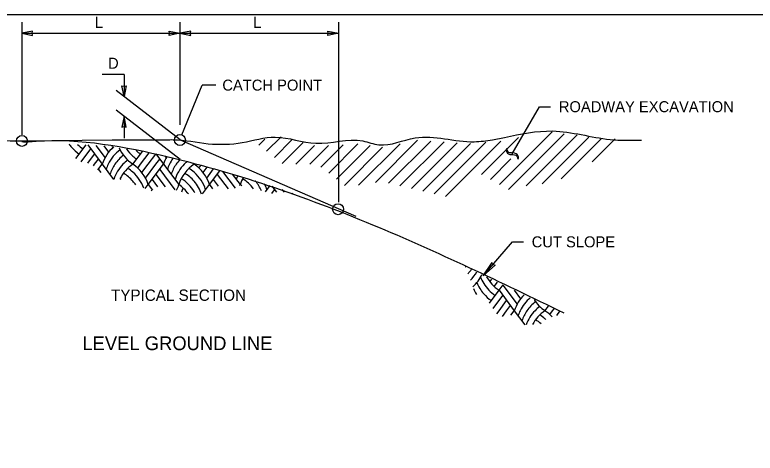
# Model space of a CAD drawing. Extents: x 99862 to 103151, y 100000 to 102076.
# Drawn here: x 100486 to 101562, y 101437 to 102076 of the extents above; entities that cross this region are included whole.
import ezdxf

# ---------------------------------------------------------------- set-up
doc = ezdxf.new("R2010")
doc.units = 0
for name, color, linetype in [('Level 1', 7, 'Continuous'), ('Level 14', 7, 'Continuous'), ('Level 15', 7, 'Continuous'), ('Level 16', 7, 'Continuous'), ('Level 17', 7, 'Continuous'), ('Level 20', 7, 'Continuous'), ('Level 4', 7, 'Continuous')]:
    doc.layers.add(name, color=color, linetype=linetype)

msp = doc.modelspace()

# ---------------------------------------------------------------- linework, layer by layer
at = {"layer": 'Level 1'}
msp.add_lwpolyline([(99862, 99999.5), (103151, 99999.5), (103151, 102075.5), (99862, 102075.5)], close=True, dxfattribs=at)
msp.add_spline([(100496.05863745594, 101891.01354403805), (100500.70108471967, 101890.4235694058), (100504.88457282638, 101890.66486915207), (100697.00538377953, 101871.58962349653), (101005.90092316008, 101770.05218203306), (101284.27137914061, 101641.69274742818)], degree=3, dxfattribs=at)
at = {"layer": 'Level 14'}
msp.add_circle((100495.98320228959, 101891.9961635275), 8, dxfattribs=at)
at = {"layer": 'Level 15'}
for p, q in [((100495.86601442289, 102064.5580484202), (100495.86601442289, 102024.27183196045)), ((100725.79867422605, 102064.5580484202), (100725.79867422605, 101915.37950221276)), ((100956.53789870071, 102064.5580484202), (100956.53789870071, 101802.89925094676)), ((100495.86601442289, 102048.5580484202), (100725.79867422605, 102048.5580484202)), ((100725.79867422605, 102048.5580484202), (100925.76532916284, 102048.5580484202)), ((100925.76532916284, 102048.5580484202), (100956.53789870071, 102048.5580484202)), ((100495.86601442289, 102024.27183196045), (100495.86601442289, 101900.69973032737)), ((100644.49165007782, 101988.4719941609), (100612.49165007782, 101988.4719941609)), ((100644.49165007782, 101988.4719941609), (100644.49165007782, 101956.4719941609)), ((100728.80250451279, 101900.68710735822), (100758.1635567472, 101973.16186250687)), ((100778.01844406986, 101973.16186250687), (100758.1635567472, 101973.16186250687)), ((100726.13895795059, 101893.31169181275), (100633.14329276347, 101965.25079774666)), ((101209.18553844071, 101873.14949087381), (101248.80950513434, 101941.78021440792)), ((101248.81060001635, 101941.78036938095), (101264.81060001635, 101941.78036938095)), ((100726.13895795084, 101864.74905572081), (100633.14329276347, 101936.68816165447)), ((100644.49165007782, 101927.9093580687), (100644.49165007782, 101895.9093580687)), ((101167.01985588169, 101695.75861149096), (101209.36149090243, 101745.07580875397)), ((101209.3623586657, 101745.07580783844), (101225.3623586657, 101745.07580783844))]:
    msp.add_line(p, q, dxfattribs=at)
for points in [[(100495.86601442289, 102048.5580484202), (100511.5910144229, 102045.47404842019), (100510.8630144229, 102048.5580484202), (100511.5910144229, 102051.6420484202)], [(100725.79867422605, 102048.5580484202), (100710.07367422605, 102045.47404842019), (100710.80167422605, 102048.5580484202), (100710.07367422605, 102051.6420484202)], [(100725.79867422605, 102048.5580484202), (100741.52367422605, 102045.47404842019), (100740.79567422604, 102048.5580484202), (100741.52367422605, 102051.6420484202)], [(100956.53789870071, 102048.5580484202), (100940.81289870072, 102045.47404842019), (100941.54089870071, 102048.5580484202), (100940.81289870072, 102051.6420484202)], [(100644.49165007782, 101956.4719941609), (100641.40765007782, 101972.1969941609), (100644.49165007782, 101971.4689941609), (100647.57565007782, 101972.1969941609)], [(100644.49165007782, 101927.9093580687), (100641.40765007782, 101912.18435806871), (100644.49165007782, 101912.9123580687), (100647.57565007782, 101912.18435806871)], [(101167.01985588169, 101695.75861149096), (101179.62609206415, 101715.02402805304), (101181.2030007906, 101712.2783551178), (101184.15633835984, 101711.13587045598)]]:
    msp.add_lwpolyline(points, close=True, dxfattribs=at)
for centre in [(100725.79867422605, 101893.27245944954), (100955.793750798, 101792.61167141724)]:
    msp.add_circle(centre, 8, dxfattribs=at)
at = {"layer": 'Level 16'}
for p, q in [((100495.98320228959, 101891.9961635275), (100627.37406219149, 101893.7652560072)), ((100627.37406219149, 101893.7652560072), (100668.42938273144, 101893.76525600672)), ((100668.42938273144, 101893.76525600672), (100710.883593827, 101893.76525600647)), ((100726.13895795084, 101893.31169181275), (100981.69296479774, 101782.6319859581)), ((101180.29869251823, 101893.60864530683), (101197.72951781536, 101896.90455149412))]:
    msp.add_line(p, q, dxfattribs=at)
for points in [[(100081.27401077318, 101899.13021604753), (100428.58825991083, 101892.98942238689), (100495.98320228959, 101891.9961635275)], [(100710.883593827, 101893.76525600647), (100716.06295287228, 101893.76525600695), (100767.04438142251, 101887.89181953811), (100816.45684165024, 101889.6713524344), (100864.47894699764, 101897.48890446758), (100923.66898382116, 101888.55455928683), (100991.79336582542, 101891.90493872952), (101015.24602192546, 101886.32097299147), (101067.7352998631, 101896.37211132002), (101153.72837222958, 101890.78814558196), (101180.29869251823, 101893.60864530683)], [(101197.72951781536, 101896.90455149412), (101267.6412732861, 101906.42324964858), (101351.40075935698, 101894.13852502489), (101397.18927840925, 101893.02173187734)]]:
    msp.add_spline(points, degree=3, dxfattribs=at)
at = {"layer": 'Level 17'}
for p, q in [((100851.80965612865, 101876.84979885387), (100873.06338126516, 101898.1035239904)), ((101190.49601222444, 101828.60732428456), (101266.96154589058, 101905.07285795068)), ((101203.54213233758, 101821.28876909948), (101284.40436457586, 101902.15100133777)), ((101229.1329203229, 101826.51488178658), (101303.23803501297, 101900.61999647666)), ((101252.69083304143, 101829.7081192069), (101320.4207297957, 101897.43801596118)), ((100840.37196178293, 101885.77677980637), (100849.12978754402, 101894.53460556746)), ((100840.37196178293, 101885.77677980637), (100849.12978754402, 101894.53460556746)), ((100863.24735047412, 101867.92281790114), (100889.15804400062, 101893.83351142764)), ((100874.68504481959, 101858.9958369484), (100905.25270673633, 101889.56349886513)), ((100874.68504481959, 101858.9958369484), (100905.25270673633, 101889.56349886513)), ((100930.71467104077, 101853.93143727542), (100963.26827372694, 101886.48503996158)), ((100930.71467104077, 101853.93143727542), (100963.26827372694, 101886.48503996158)), ((100942.15236538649, 101845.00445632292), (100984.7047740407, 101887.55686497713)), ((100985.60700871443, 101827.36507375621), (101046.06243116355, 101887.82049620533)), ((101010.14905330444, 101831.542443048), (101071.51827528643, 101892.91166503)), ((101029.26210287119, 101830.29081731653), (101090.72224167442, 101891.75095611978)), ((101029.26210287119, 101830.29081731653), (101090.72224167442, 101891.75095611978)), ((101045.80840155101, 101826.47244069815), (101109.86012930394, 101890.52416845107)), ((101062.3547002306, 101822.65406407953), (101128.99801693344, 101889.29738078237)), ((101078.90099891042, 101818.83568746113), (101148.13590456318, 101888.0705931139)), ((101078.90099891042, 101818.83568746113), (101148.13590456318, 101888.0705931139)), ((101095.44729759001, 101815.01731084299), (101170.47848281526, 101890.04849606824)), ((101111.99359626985, 101811.19893422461), (101192.31778782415, 101891.52312577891)), ((101164.4037719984, 101843.24443465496), (101218.08888410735, 101896.9295467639)), ((101280.11420253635, 101836.7668134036), (101338.42042397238, 101895.07303483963)), ((101280.11420253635, 101836.7668134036), (101338.42042397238, 101895.07303483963)), ((101325.3683803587, 101861.65631592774), (101358.78509927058, 101895.07303483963)), ((100894.23478513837, 101858.18090196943), (100921.3473694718, 101885.29348630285)), ((100914.59946043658, 101858.18090196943), (100941.83177341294, 101885.4132149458)), ((100953.59005973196, 101836.07747537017), (101002.67182793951, 101885.15924357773)), ((100965.02775407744, 101827.15049441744), (101020.60658704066, 101882.72932738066)), ((100965.02775407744, 101827.15049441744), (101020.60658704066, 101882.72932738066)), ((101164.4037719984, 101843.24443465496), (101193.10420883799, 101871.94487149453)), ((101177.4498921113, 101835.92587946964), (101207.23710234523, 101865.71308970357)), ((101203.54213233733, 101821.28876909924), (101203.54213233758, 101821.28876909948)), ((101203.54213233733, 101821.28876909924), (101203.54213233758, 101821.28876909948))]:
    msp.add_line(p, q, dxfattribs=at)
at = {"layer": 'Level 20'}
for p, q in [((101200.132406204, 101879.2271412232), (101200.49340620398, 101877.1111412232)), ((101201.18954344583, 101881.05771042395), (101200.13256746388, 101879.22669653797)), ((101200.49340620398, 101877.1111412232), (101201.13840620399, 101875.45314122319)), ((101202.17240620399, 101877.49514122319), (101201.189406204, 101881.0581412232)), ((101203.04440620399, 101876.09814122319), (101202.17240620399, 101877.49514122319)), ((101204.12840620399, 101875.1791412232), (101203.04440620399, 101876.09814122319)), ((101201.13840620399, 101875.45314122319), (101202.09540620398, 101874.15114122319)), ((101202.09540620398, 101874.15114122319), (101203.42140620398, 101873.14714122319)), ((101203.42140620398, 101873.14714122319), (101205.71940620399, 101872.25314122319)), ((101205.53240620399, 101874.6481412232), (101204.12840620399, 101875.1791412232)), ((101207.94740620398, 101874.4441412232), (101205.53240620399, 101874.6481412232)), ((101205.71940620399, 101872.25314122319), (101209.80140620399, 101871.9891412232)), ((101212.34340620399, 101874.07114122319), (101207.94740620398, 101874.4441412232)), ((101209.80140620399, 101871.9891412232), (101212.34240620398, 101871.7631412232)), ((101212.34240620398, 101871.7631412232), (101214.155406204, 101871.13114122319)), ((101214.90040620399, 101873.1421412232), (101212.34340620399, 101874.07114122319)), ((101214.155406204, 101871.13114122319), (101215.204406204, 101870.30914122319)), ((101216.299406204, 101872.07114122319), (101214.90040620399, 101873.1421412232)), ((101215.204406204, 101870.30914122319), (101216.01040620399, 101869.2121412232)), ((101216.01040620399, 101869.2121412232), (101216.63040620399, 101867.5911412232)), ((101217.31640620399, 101870.7011412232), (101216.299406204, 101872.07114122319)), ((101216.63040620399, 101867.5911412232), (101217.14740620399, 101865.22214122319)), ((101217.14754191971, 101865.22189631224), (101218.20408493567, 101867.05216017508)), ((101217.94940620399, 101869.02514122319), (101217.31640620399, 101870.7011412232)), ((101218.204406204, 101867.05214122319), (101217.94940620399, 101869.02514122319))]:
    msp.add_line(p, q, dxfattribs=at)
at = {"layer": 'Level 4'}
for p, q in [((100574.5049341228, 101866.27232183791), (100589.4552151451, 101886.2060299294)), ((100582.06035984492, 101861.49698034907), (100596.1485173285, 101880.2811903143)), ((100591.80365367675, 101886.07434178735), (100612.85391496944, 101858.00732670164)), ((100603.42952392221, 101885.42242382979), (100616.86551804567, 101867.50776500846)), ((100615.0553942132, 101884.7705058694), (100622.03057026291, 101875.47027117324)), ((100626.99100618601, 101883.70559896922), (100628.14650995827, 101882.16492727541)), ((100657.40018778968, 101858.00732670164), (100671.24296921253, 101876.46436865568)), ((100591.86085983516, 101859.71507125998), (100601.71698325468, 101872.85656912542)), ((100601.71697501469, 101858.00731576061), (100607.28544913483, 101865.4319479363)), ((100668.5371114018, 101858.00731576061), (100681.16250367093, 101874.84117210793)), ((100679.67404320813, 101858.00731576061), (100690.81098325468, 101872.85656912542)), ((100690.63258366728, 101873.09443511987), (100701.94791496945, 101858.00732670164)), ((100690.81097501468, 101858.00731576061), (100696.37944913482, 101865.4319479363)), ((100704.39339991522, 101869.59592251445), (100705.95951804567, 101867.50776500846)), ((100600.03724935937, 101855.76762106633), (100601.71702038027, 101858.00731576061)), ((100606.65324846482, 101849.73971077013), (100612.8539148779, 101858.00726600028)), ((100612.8539148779, 101858.00726600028), (100629.40096058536, 101835.94453840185)), ((100664.38145627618, 101852.46638177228), (100668.5371567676, 101858.00731576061)), ((100670.49739597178, 101845.7717256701), (100679.67408857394, 101858.00731576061)), ((100675.66244818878, 101837.80921950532), (100690.81102038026, 101858.00731576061)), ((100679.67405131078, 101828.3087811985), (100701.94791487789, 101858.00726600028)), ((100701.94791487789, 101858.00726600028), (100724.22177849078, 101828.3087811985)), ((100746.49418778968, 101858.00732670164), (100747.05164687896, 101858.75060548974)), ((100753.47545627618, 101852.46638177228), (100756.40512237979, 101856.37260324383)), ((100607.2854489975, 101850.58264476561), (100610.64609383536, 101846.10178498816)), ((100696.3794489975, 101850.58264476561), (100718.62717994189, 101820.91900354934)), ((100759.59139597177, 101845.7717256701), (100765.62503189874, 101853.8165735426)), ((100764.75644818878, 101837.80921950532), (100774.8101303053, 101851.21412899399)), ((100768.76805131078, 101828.3087811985), (100783.9952287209, 101848.61168444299)), ((100787.74943890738, 101847.54799155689), (100806.08815234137, 101823.09637368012)), ((100801.89157453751, 101843.54105312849), (100813.31577849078, 101828.3087811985)), ((100685.24251719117, 101835.73340238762), (100693.21737300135, 101825.10026131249)), ((100690.81098307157, 101843.1580235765), (100704.27498328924, 101825.20602332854)), ((100774.33651719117, 101835.73340238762), (100781.59264180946, 101826.05856956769)), ((100779.90498307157, 101843.1580235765), (100795.71753092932, 101822.07462648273)), ((100675.37887563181, 101822.58188022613), (100679.67405135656, 101828.3087811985)), ((100679.67405131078, 101828.3087811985), (100685.79275181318, 101820.15051385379)), ((100758.79437849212, 101815.01055069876), (100768.76805135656, 101828.3087811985)), ((100768.76805131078, 101828.3087811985), (100773.2178438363, 101822.3757244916)), ((100850.02400241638, 101817.85804926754), (100856.83405578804, 101826.9381204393)), ((100859.54224949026, 101826.0685169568), (100866.16531284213, 101817.23776581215)), ((100684.03203127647, 101819.27017868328), (100685.24251723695, 101820.88415996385)), ((100859.40247129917, 101815.5134320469), (100863.43051723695, 101820.88415996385)), ((100874.2120448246, 101821.35803221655), (100877.30174867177, 101817.23842708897)), ((100888.88184020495, 101816.64754746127), (100889.6761173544, 101815.58851126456)), ((101176.71626141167, 101686.78233009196), (101179.54267063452, 101690.55087571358)), ((101182.83220110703, 101680.087673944), (101187.67490598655, 101686.54461377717)), ((101189.81346973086, 101674.54678962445), (101195.8153253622, 101682.54926381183)), ((101195.38193561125, 101681.97141081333), (101216.09893641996, 101654.34874308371)), ((101175.83065047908, 101655.90303056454), (101189.81346973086, 101674.54678962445)), ((101189.81346973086, 101674.54678962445), (101212.08733334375, 101644.84830477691)), ((101212.00678279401, 101674.65419032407), (101221.2639886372, 101662.31124924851)), ((101181.16986307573, 101648.17273823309), (101195.3819357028, 101667.12216838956)), ((101189.81346158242, 101644.84829383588), (101200.95040162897, 101659.69754720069)), ((101200.950393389, 101644.84829383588), (101206.51886750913, 101652.27292601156)), ((101256.63360616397, 101644.84830477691), (101261.59861765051, 101651.4683201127)), ((101186.5090973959, 101640.44241444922), (101189.81350694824, 101644.84829383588)), ((101194.73919465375, 101636.5666350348), (101200.95043875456, 101644.84829383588)), ((101207.05533102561, 101638.13890776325), (101212.08733325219, 101644.84824407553)), ((101212.08733325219, 101644.84824407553), (101227.57452213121, 101624.19865891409)), ((101263.61487465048, 101639.30735984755), (101267.77057514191, 101644.84829383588)), ((101267.7705297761, 101644.84829383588), (101269.97198701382, 101647.78357015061)), ((101273.80318995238, 101638.04253786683), (101278.38365789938, 101644.14982843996))]:
    msp.add_line(p, q, dxfattribs=at)
for centre, radius, start, end in [((100610.88545334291, 101919.63916991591), 56.36613020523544, 214.633380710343, 220.94160750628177), ((100616.45246486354, 101927.06379110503), 56.36613020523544, 225.42789081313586, 236.09639215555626), ((100610.88399893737, 101919.63916991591), 56.36613020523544, 220.94153677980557, 236.09639215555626), ((100666.56865787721, 101840.9232107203), 56.366130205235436, 131.23797718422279, 162.35659680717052), ((100672.13712380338, 101833.4985894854), 56.366130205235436, 126.30625461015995, 154.22660450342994), ((100688.84252153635, 101904.78992749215), 56.36613020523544, 203.8239796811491, 236.09639215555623), ((100694.41098746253, 101912.21454872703), 56.36613020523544, 214.51920153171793, 228.95991963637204), ((100699.97799893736, 101919.63916991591), 56.36613020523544, 227.66169890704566, 236.09639215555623), ((100677.70558968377, 101826.07396829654), 56.366130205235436, 127.10060074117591, 145.49109452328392), ((100694.40953305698, 101912.21454872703), 56.36613020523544, 228.95985818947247, 236.09639215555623), ((100755.66265787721, 101840.9232107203), 56.366130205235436, 150.1375585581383, 162.35659680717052), ((100761.23112380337, 101833.4985894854), 56.366130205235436, 143.88392968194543, 154.22660450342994), ((100672.13712371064, 101833.49852887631), 56.366130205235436, 154.2265360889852, 162.35659667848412), ((100677.70558959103, 101826.07390768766), 56.366130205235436, 145.49101975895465, 162.35659667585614), ((100683.2740555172, 101818.64928649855), 56.366130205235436, 135.7126927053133, 162.07204112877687), ((100688.84252139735, 101811.22466526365), 56.366130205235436, 123.90360784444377, 153.15676788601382), ((100683.27405560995, 101818.6493471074), 56.366130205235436, 126.33099923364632, 135.7127787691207), ((100625.9593083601, 101811.22466521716), 56.36613020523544, 17.643403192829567, 56.09634079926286), ((100761.23112371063, 101833.49852887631), 56.366130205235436, 154.2265360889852, 162.35659667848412), ((100766.79958959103, 101826.07390768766), 56.366130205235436, 145.49101975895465, 162.35659667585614), ((100772.3680555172, 101818.64928649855), 56.366130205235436, 135.7126927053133, 162.35659671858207), ((100766.79958968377, 101826.07396829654), 56.366130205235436, 137.34218587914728, 145.49109452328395), ((100777.93652139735, 101811.22466526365), 56.366130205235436, 123.90360784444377, 162.3565968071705), ((100772.36805560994, 101818.6493471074), 56.366130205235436, 130.36652356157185, 135.7127787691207), ((100777.93652153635, 101904.78992749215), 56.36613020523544, 233.64906575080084, 236.09639215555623), ((100715.0533083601, 101811.22466521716), 56.36613020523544, 17.643403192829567, 56.09634079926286), ((100614.82383095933, 101796.3754227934), 56.36613020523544, 40.94133610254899, 59.30214645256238), ((100620.39229683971, 101803.80004398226), 56.36613020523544, 48.95968384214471, 58.54646196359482), ((100620.39084243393, 101803.80004398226), 56.36613020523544, 20.349093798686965, 48.9597452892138), ((100703.91783095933, 101796.3754227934), 56.36613020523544, 40.94133610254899, 59.30214645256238), ((100709.48629683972, 101803.80004398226), 56.36613020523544, 48.95968384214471, 58.54646196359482), ((100709.48484243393, 101803.80004398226), 56.36613020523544, 17.643403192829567, 48.9597452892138), ((100855.89358959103, 101826.07390768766), 56.366130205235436, 162.0614234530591, 162.3565966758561), ((100609.25536503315, 101788.95080160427), 56.36613020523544, 56.62365922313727, 58.48736525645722), ((100614.82237655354, 101796.3754227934), 56.36613020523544, 33.96477581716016, 40.941406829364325), ((100698.34936503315, 101788.95080160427), 56.36613020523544, 31.3316299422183, 58.487365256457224), ((100703.91637655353, 101796.3754227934), 56.36613020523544, 18.520508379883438, 40.941406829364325), ((100861.4620555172, 101818.64928649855), 56.366130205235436, 156.3190310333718, 162.35659671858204), ((100867.03052139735, 101811.22466526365), 56.366130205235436, 150.49569783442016, 162.3565968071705), ((100787.44336503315, 101788.95080160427), 56.36613020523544, 36.03215682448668, 58.48736525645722), ((100793.01183095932, 101796.3754227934), 56.36613020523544, 40.94133610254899, 41.78792432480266), ((100793.01037655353, 101796.3754227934), 56.36613020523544, 23.92067132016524, 40.941406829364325), ((100670.50703549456, 101845.39289718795), 56.36613020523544, 333.4826156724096, 342.3565968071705), ((100692.78089915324, 101781.52618036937), 56.36613020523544, 36.58292861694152, 56.096392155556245), ((100676.07550137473, 101837.96827595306), 56.36613020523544, 339.1391139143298, 345.0112638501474), ((100759.60103549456, 101845.39289718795), 56.36613020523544, 341.0971026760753, 342.3565968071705), ((100781.87489915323, 101781.52618036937), 56.36613020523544, 52.68022749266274, 56.096392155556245), ((100798.57884243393, 101803.80004398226), 56.36613020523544, 17.643403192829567, 27.174407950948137), ((100681.6439673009, 101830.54365476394), 56.36613020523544, 344.75444342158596, 346.3198811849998), ((100698.34791062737, 101788.95080160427), 56.36613020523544, 29.18587849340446, 31.331719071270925), ((101097.12091974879, 101743.60325402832), 56.36613020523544, 321.48406270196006, 322.24554323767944), ((101102.68938567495, 101736.1786328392), 56.36613020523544, 318.32191749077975, 326.6301018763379), ((101108.25785155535, 101728.75401165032), 56.36613020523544, 315.2513206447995, 330.9404336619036), ((101113.82631748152, 101721.32939041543), 56.36613020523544, 312.25659208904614, 335.22697607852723), ((101215.68733764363, 101713.9047691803), 56.36613020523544, 200.87780938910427, 211.33197196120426), ((101221.25434911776, 101721.3293904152), 56.36613020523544, 208.54619772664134, 236.09639215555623), ((101210.11887171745, 101706.48014799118), 56.36613020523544, 201.4343785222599, 220.94160750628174), ((101215.68588323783, 101713.9047691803), 56.36613020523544, 211.33188283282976, 236.0963921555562), ((101204.55040583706, 101699.0555268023), 56.36613020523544, 203.04574707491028, 212.6840840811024), ((101210.11741731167, 101706.48014799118), 56.36613020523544, 220.94153677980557, 236.09639215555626), ((101265.80207625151, 101627.76418879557), 56.366130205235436, 134.68000398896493, 162.35659680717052), ((101271.37054217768, 101620.33956756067), 56.366130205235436, 129.92426670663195, 154.22660450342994), ((101288.0759399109, 101691.6309055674), 56.36613020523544, 212.9842791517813, 236.09639215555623), ((101276.93900805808, 101612.91494637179), 56.366130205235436, 127.10060074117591, 145.49109452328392), ((101282.50747398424, 101605.49032518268), 56.366130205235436, 126.33099923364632, 135.7127787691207), ((101271.37054208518, 101620.33950695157), 56.366130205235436, 154.2265360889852, 162.35659667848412), ((101276.93900796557, 101612.91488576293), 56.366130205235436, 145.49101975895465, 162.35659667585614), ((101282.50747389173, 101605.49026457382), 56.366130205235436, 135.7126927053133, 160.47946871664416), ((101288.07593977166, 101598.06564333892), 56.366130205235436, 123.90360784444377, 151.49701199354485), ((101219.62571521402, 101590.64102205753), 56.36613020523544, 48.95968384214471, 58.54646196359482), ((101225.19272673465, 101598.06564329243), 56.36613020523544, 41.913176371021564, 56.09634079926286), ((101214.05724933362, 101583.21640086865), 56.36613020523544, 49.11356384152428, 59.30214645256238), ((101219.62426080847, 101590.64102205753), 56.36613020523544, 47.00022190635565, 48.9597452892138)]:
    msp.add_arc(centre, radius, start, end, dxfattribs=at)

# ---------------------------------------------------------------- texts
at = {"layer": 'Level 15'}
msp.add_text('D', height=16, dxfattribs=at).set_placement((100621.24653289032, 101996.9719941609))
at = {"layer": 'Level 20'}
for s, height, p in [('L ', 16.5, (100601.91162899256, 102056.3080484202)), ('L ', 16.5, (100832.24757113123, 102056.3080484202)), ('CATCH POINT', 16, (100787.47356997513, 101965.16186250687)), ('ROADWAY EXCAVATION', 16, (101276.81060001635, 101933.78036938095)), ('CUT SLOPE', 16, (101237.3623586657, 101737.07580783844)), ('TYPICAL SECTION', 16.5, (100625.71505606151, 101659.20881875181)), ('LEVEL GROUND LINE', 19.999997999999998, (100583.92612981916, 101587.45881975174))]:
    msp.add_text(s, height=height, dxfattribs=at).set_placement(p)

doc.saveas('drawing.dxf')
